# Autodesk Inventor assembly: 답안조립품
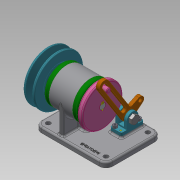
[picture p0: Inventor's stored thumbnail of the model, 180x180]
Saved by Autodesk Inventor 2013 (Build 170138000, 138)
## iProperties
Created: 2019-09
Part Number: 답안조립품
Document SubType Name: Assembly
Designer: Administrator
Author: Administrator
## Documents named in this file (19)
- C:\Users\Administrator\Desktop\390904V1010\답안조립품.iam
- C:\Users\Administrator\Desktop\390904V1010\본체.ipt
- C:\Users\Administrator\Desktop\390904V1010\V-벨트풀리.ipt
- C:\Users\Administrator\Desktop\390904V1010\너트 M8.ipt
- C:\Users\Administrator\Desktop\390904V1010\너트 M10x1.ipt
- C:\Users\Administrator\Desktop\390904V1010\돌림판.ipt
- C:\Users\Administrator\Desktop\390904V1010\멈춤나사 M3x5.ipt
- C:\Users\Administrator\Desktop\390904V1010\베어링 6004.ipt
- C:\Users\Administrator\Desktop\390904V1010\볼트 M4.ipt
- C:\Users\Administrator\Desktop\390904V1010\오일 실 17 30 5.ipt
- C:\Users\Administrator\Desktop\390904V1010\와셔 8x15.5.ipt
- C:\Users\Administrator\Desktop\390904V1010\축.ipt
- C:\Users\Administrator\Desktop\390904V1010\커버.ipt
- C:\Users\Administrator\Desktop\390904V1010\크랭크.ipt
- C:\Users\Administrator\Desktop\390904V1010\키 4 x 4 x 8.ipt
- C:\Users\Administrator\Desktop\390904V1010\키 5 x 5 x 12.ipt
- C:\Users\Administrator\Desktop\390904V1010\핀 3 x 8.ipt
- C:\Users\Administrator\Desktop\390904V1010\힌지 축.ipt
- C:\Users\Administrator\Desktop\390904V1010\힌지.ipt
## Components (3 placed, 2 different names)
1. V-벨트풀리:1
2. 핀 3 x 8:1 — 플러쉬:1
3. 핀 3 x 8:2 — 플러쉬:2
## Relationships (2: Flush 2)
- 플러쉬:1 [Flush]: 핀 3 x 8:1
- 플러쉬:2 [Flush]: 핀 3 x 8:2
